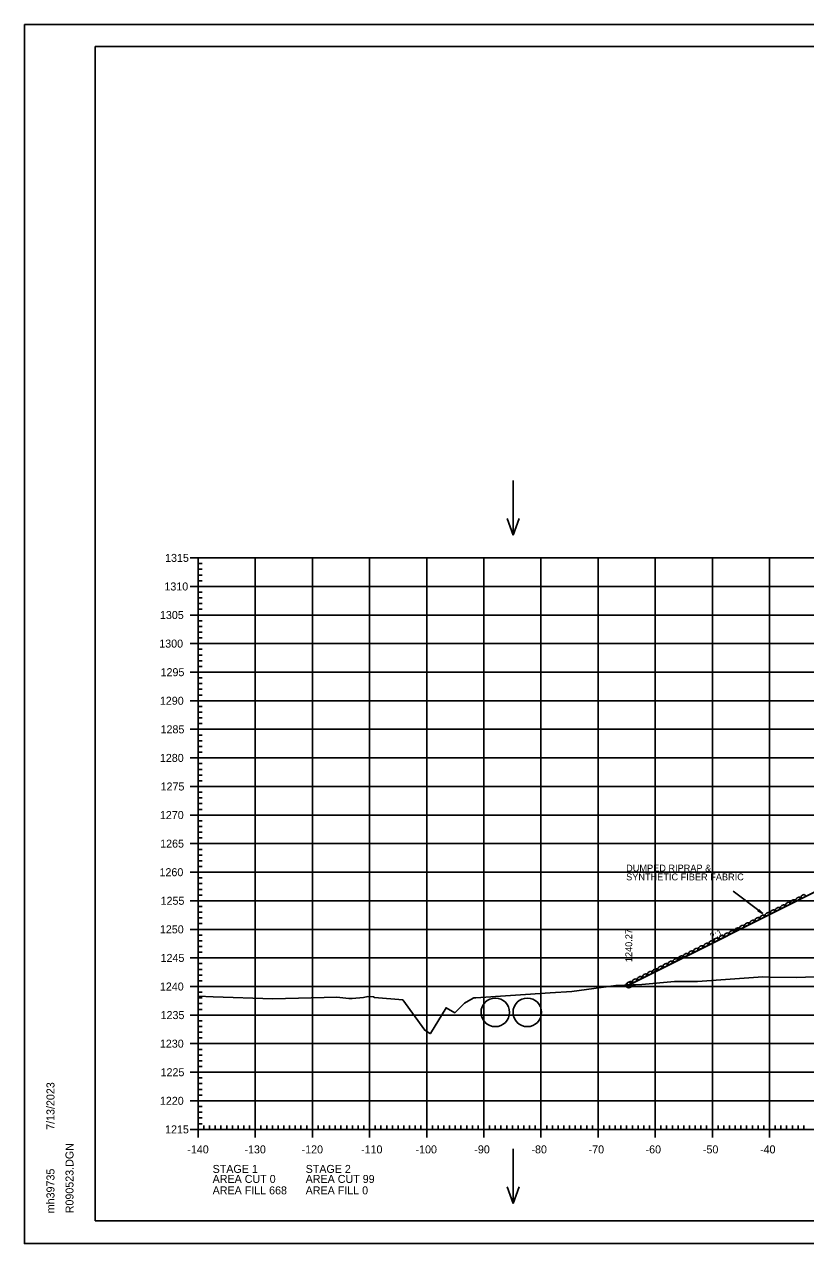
# Model space of a CAD drawing. Extents: x 1406028 to 1412453, y 321733 to 325986.
# Drawn here: x 1406419.5 to 1406556.2, y 323639.4 to 323852.7 of the extents above; entities that cross this region are included whole.
import ezdxf

# ---------------------------------------------------------------- set-up
doc = ezdxf.new("R2010")
doc.units = 0
for name, color, linetype in [('R_Axis', 7, 'Continuous'), ('R_Axis Annot', 7, 'Continuous'), ('R_Border', 7, 'Continuous'), ('R_Draft', 7, 'Continuous'), ('R_Exist Surface', 7, 'Continuous'), ('R_Fin Surface', 7, 'Continuous'), ('R_Fin Surface Annot', 7, 'Continuous'), ('R_Grid', 7, 'Continuous'), ('R_No Plot', 7, 'Continuous'), ('R_Proposed Const Limits', 7, 'Continuous'), ('R_Water', 7, 'Continuous'), ('R_Water Annot', 7, 'Continuous')]:
    doc.layers.add(name, color=color, linetype=linetype)

msp = doc.modelspace()

# ---------------------------------------------------------------- linework, layer by layer
at = {"layer": 'R_Axis'}
for p, q in [((1406448.49, 323759.36), (1406451.29, 323759.36)), ((1406449.89, 323659.36), (1406449.89, 323759.36)), ((1406449.89, 323758.36), (1406450.59, 323758.36)), ((1406449.89, 323757.36), (1406450.59, 323757.36)), ((1406449.89, 323756.36), (1406450.59, 323756.36)), ((1406449.89, 323755.36), (1406450.59, 323755.36)), ((1406448.49, 323754.36), (1406451.29, 323754.36)), ((1406449.89, 323753.36), (1406450.59, 323753.36)), ((1406449.89, 323752.36), (1406450.59, 323752.36)), ((1406449.89, 323751.36), (1406450.59, 323751.36)), ((1406448.49, 323749.36), (1406451.29, 323749.36)), ((1406449.89, 323750.36), (1406450.59, 323750.36)), ((1406449.89, 323748.36), (1406450.59, 323748.36)), ((1406449.89, 323747.36), (1406450.59, 323747.36)), ((1406449.89, 323746.36), (1406450.59, 323746.36)), ((1406448.49, 323744.36), (1406451.29, 323744.36)), ((1406449.89, 323745.36), (1406450.59, 323745.36)), ((1406449.89, 323743.36), (1406450.59, 323743.36)), ((1406449.89, 323742.36), (1406450.59, 323742.36)), ((1406449.89, 323741.36), (1406450.59, 323741.36)), ((1406449.89, 323740.36), (1406450.59, 323740.36)), ((1406448.49, 323739.36), (1406451.29, 323739.36)), ((1406449.89, 323738.36), (1406450.59, 323738.36)), ((1406449.89, 323737.36), (1406450.59, 323737.36)), ((1406449.89, 323736.36), (1406450.59, 323736.36)), ((1406448.49, 323734.36), (1406451.29, 323734.36)), ((1406449.89, 323735.36), (1406450.59, 323735.36)), ((1406449.89, 323733.36), (1406450.59, 323733.36)), ((1406449.89, 323732.36), (1406450.59, 323732.36)), ((1406449.89, 323731.36), (1406450.59, 323731.36)), ((1406448.49, 323729.36), (1406451.29, 323729.36)), ((1406449.89, 323730.36), (1406450.59, 323730.36)), ((1406449.89, 323728.36), (1406450.59, 323728.36)), ((1406449.89, 323727.36), (1406450.59, 323727.36)), ((1406449.89, 323726.36), (1406450.59, 323726.36)), ((1406449.89, 323725.36), (1406450.59, 323725.36)), ((1406448.49, 323724.36), (1406451.29, 323724.36)), ((1406449.89, 323723.36), (1406450.59, 323723.36)), ((1406449.89, 323722.36), (1406450.59, 323722.36)), ((1406449.89, 323721.36), (1406450.59, 323721.36)), ((1406448.49, 323719.36), (1406451.29, 323719.36)), ((1406449.89, 323720.36), (1406450.59, 323720.36)), ((1406449.89, 323718.36), (1406450.59, 323718.36)), ((1406449.89, 323717.36), (1406450.59, 323717.36)), ((1406449.89, 323716.36), (1406450.59, 323716.36)), ((1406448.49, 323714.36), (1406451.29, 323714.36)), ((1406449.89, 323715.36), (1406450.59, 323715.36)), ((1406449.89, 323713.36), (1406450.59, 323713.36)), ((1406449.89, 323712.36), (1406450.59, 323712.36)), ((1406449.89, 323711.36), (1406450.59, 323711.36)), ((1406449.89, 323710.36), (1406450.59, 323710.36)), ((1406448.49, 323709.36), (1406451.29, 323709.36)), ((1406449.89, 323708.36), (1406450.59, 323708.36)), ((1406449.89, 323707.36), (1406450.59, 323707.36)), ((1406449.89, 323706.36), (1406450.59, 323706.36)), ((1406448.49, 323704.36), (1406451.29, 323704.36)), ((1406449.89, 323705.36), (1406450.59, 323705.36)), ((1406449.89, 323703.36), (1406450.59, 323703.36)), ((1406449.89, 323702.36), (1406450.59, 323702.36)), ((1406448.49, 323699.36), (1406451.29, 323699.36)), ((1406449.89, 323701.36), (1406450.59, 323701.36)), ((1406449.89, 323700.36), (1406450.59, 323700.36)), ((1406449.89, 323698.36), (1406450.59, 323698.36)), ((1406449.89, 323697.36), (1406450.59, 323697.36)), ((1406449.89, 323696.36), (1406450.59, 323696.36)), ((1406449.89, 323695.36), (1406450.59, 323695.36)), ((1406448.49, 323694.36), (1406451.29, 323694.36)), ((1406449.89, 323693.36), (1406450.59, 323693.36)), ((1406449.89, 323692.36), (1406450.59, 323692.36)), ((1406449.89, 323691.36), (1406450.59, 323691.36)), ((1406448.49, 323689.36), (1406451.29, 323689.36)), ((1406449.89, 323690.36), (1406450.59, 323690.36)), ((1406449.89, 323688.36), (1406450.59, 323688.36)), ((1406449.89, 323687.36), (1406450.59, 323687.36)), ((1406448.49, 323684.36), (1406451.29, 323684.36)), ((1406449.89, 323686.36), (1406450.59, 323686.36)), ((1406449.89, 323685.36), (1406450.59, 323685.36)), ((1406449.89, 323683.36), (1406450.59, 323683.36)), ((1406449.89, 323682.36), (1406450.59, 323682.36)), ((1406449.89, 323681.36), (1406450.59, 323681.36)), ((1406449.89, 323680.36), (1406450.59, 323680.36)), ((1406448.49, 323679.36), (1406451.29, 323679.36)), ((1406449.89, 323678.36), (1406450.59, 323678.36)), ((1406449.89, 323677.36), (1406450.59, 323677.36)), ((1406449.89, 323676.36), (1406450.59, 323676.36)), ((1406448.49, 323674.36), (1406451.29, 323674.36)), ((1406449.89, 323675.36), (1406450.59, 323675.36)), ((1406449.89, 323673.36), (1406450.59, 323673.36)), ((1406449.89, 323672.36), (1406450.59, 323672.36)), ((1406449.89, 323671.36), (1406450.59, 323671.36)), ((1406449.89, 323670.36), (1406450.59, 323670.36)), ((1406448.49, 323669.36), (1406451.29, 323669.36)), ((1406449.89, 323668.36), (1406450.59, 323668.36)), ((1406449.89, 323667.36), (1406450.59, 323667.36)), ((1406449.89, 323666.36), (1406450.59, 323666.36)), ((1406449.89, 323665.36), (1406450.59, 323665.36)), ((1406448.49, 323664.36), (1406451.29, 323664.36)), ((1406449.89, 323663.36), (1406450.59, 323663.36)), ((1406449.89, 323662.36), (1406450.59, 323662.36)), ((1406449.89, 323661.36), (1406450.59, 323661.36)), ((1406448.49, 323659.36), (1406451.29, 323659.36)), ((1406449.89, 323657.96), (1406449.89, 323660.76)), ((1406449.89, 323660.36), (1406450.59, 323660.36)), ((1406449.89, 323659.36), (1406729.89, 323659.36)), ((1406450.89, 323659.36), (1406450.89, 323660.06)), ((1406451.89, 323659.36), (1406451.89, 323660.06)), ((1406452.89, 323659.36), (1406452.89, 323660.06)), ((1406453.89, 323659.36), (1406453.89, 323660.06)), ((1406454.89, 323659.36), (1406454.89, 323660.06)), ((1406455.89, 323659.36), (1406455.89, 323660.06)), ((1406456.89, 323659.36), (1406456.89, 323660.06)), ((1406457.89, 323659.36), (1406457.89, 323660.06)), ((1406458.89, 323659.36), (1406458.89, 323660.06)), ((1406459.89, 323657.96), (1406459.89, 323660.76)), ((1406460.89, 323659.36), (1406460.89, 323660.06)), ((1406461.89, 323659.36), (1406461.89, 323660.06)), ((1406462.89, 323659.36), (1406462.89, 323660.06)), ((1406463.89, 323659.36), (1406463.89, 323660.06)), ((1406464.89, 323659.36), (1406464.89, 323660.06)), ((1406465.89, 323659.36), (1406465.89, 323660.06)), ((1406466.89, 323659.36), (1406466.89, 323660.06)), ((1406467.89, 323659.36), (1406467.89, 323660.06)), ((1406468.89, 323659.36), (1406468.89, 323660.06)), ((1406469.89, 323657.96), (1406469.89, 323660.76)), ((1406470.89, 323659.36), (1406470.89, 323660.06)), ((1406471.89, 323659.36), (1406471.89, 323660.06)), ((1406472.89, 323659.36), (1406472.89, 323660.06)), ((1406473.89, 323659.36), (1406473.89, 323660.06)), ((1406474.89, 323659.36), (1406474.89, 323660.06)), ((1406475.89, 323659.36), (1406475.89, 323660.06)), ((1406476.89, 323659.36), (1406476.89, 323660.06)), ((1406477.89, 323659.36), (1406477.89, 323660.06)), ((1406478.89, 323659.36), (1406478.89, 323660.06)), ((1406479.89, 323657.96), (1406479.89, 323660.76)), ((1406480.89, 323659.36), (1406480.89, 323660.06)), ((1406481.89, 323659.36), (1406481.89, 323660.06)), ((1406482.89, 323659.36), (1406482.89, 323660.06)), ((1406483.89, 323659.36), (1406483.89, 323660.06)), ((1406484.89, 323659.36), (1406484.89, 323660.06)), ((1406485.89, 323659.36), (1406485.89, 323660.06)), ((1406486.89, 323659.36), (1406486.89, 323660.06)), ((1406487.89, 323659.36), (1406487.89, 323660.06)), ((1406488.89, 323659.36), (1406488.89, 323660.06)), ((1406489.89, 323657.96), (1406489.89, 323660.76)), ((1406490.89, 323659.36), (1406490.89, 323660.06)), ((1406491.89, 323659.36), (1406491.89, 323660.06)), ((1406492.89, 323659.36), (1406492.89, 323660.06)), ((1406493.89, 323659.36), (1406493.89, 323660.06)), ((1406494.89, 323659.36), (1406494.89, 323660.06)), ((1406495.89, 323659.36), (1406495.89, 323660.06)), ((1406496.89, 323659.36), (1406496.89, 323660.06)), ((1406497.89, 323659.36), (1406497.89, 323660.06)), ((1406498.89, 323659.36), (1406498.89, 323660.06)), ((1406499.89, 323657.96), (1406499.89, 323660.76)), ((1406500.89, 323659.36), (1406500.89, 323660.06)), ((1406501.89, 323659.36), (1406501.89, 323660.06)), ((1406502.89, 323659.36), (1406502.89, 323660.06)), ((1406503.89, 323659.36), (1406503.89, 323660.06)), ((1406504.89, 323659.36), (1406504.89, 323660.06)), ((1406505.89, 323659.36), (1406505.89, 323660.06)), ((1406506.89, 323659.36), (1406506.89, 323660.06)), ((1406507.89, 323659.36), (1406507.89, 323660.06)), ((1406508.89, 323659.36), (1406508.89, 323660.06)), ((1406509.89, 323657.96), (1406509.89, 323660.76)), ((1406510.89, 323659.36), (1406510.89, 323660.06)), ((1406511.89, 323659.36), (1406511.89, 323660.06)), ((1406512.89, 323659.36), (1406512.89, 323660.06)), ((1406513.89, 323659.36), (1406513.89, 323660.06)), ((1406514.89, 323659.36), (1406514.89, 323660.06)), ((1406515.89, 323659.36), (1406515.89, 323660.06)), ((1406516.89, 323659.36), (1406516.89, 323660.06)), ((1406517.89, 323659.36), (1406517.89, 323660.06)), ((1406518.89, 323659.36), (1406518.89, 323660.06)), ((1406519.89, 323657.96), (1406519.89, 323660.76)), ((1406520.89, 323659.36), (1406520.89, 323660.06)), ((1406521.89, 323659.36), (1406521.89, 323660.06)), ((1406522.89, 323659.36), (1406522.89, 323660.06)), ((1406523.89, 323659.36), (1406523.89, 323660.06)), ((1406524.89, 323659.36), (1406524.89, 323660.06)), ((1406525.89, 323659.36), (1406525.89, 323660.06)), ((1406526.89, 323659.36), (1406526.89, 323660.06)), ((1406527.89, 323659.36), (1406527.89, 323660.06)), ((1406528.89, 323659.36), (1406528.89, 323660.06)), ((1406529.89, 323657.96), (1406529.89, 323660.76)), ((1406530.89, 323659.36), (1406530.89, 323660.06)), ((1406531.89, 323659.36), (1406531.89, 323660.06)), ((1406532.89, 323659.36), (1406532.89, 323660.06)), ((1406533.89, 323659.36), (1406533.89, 323660.06)), ((1406534.89, 323659.36), (1406534.89, 323660.06)), ((1406535.89, 323659.36), (1406535.89, 323660.06)), ((1406536.89, 323659.36), (1406536.89, 323660.06)), ((1406537.89, 323659.36), (1406537.89, 323660.06)), ((1406538.89, 323659.36), (1406538.89, 323660.06)), ((1406539.89, 323657.96), (1406539.89, 323660.76)), ((1406540.89, 323659.36), (1406540.89, 323660.06)), ((1406541.89, 323659.36), (1406541.89, 323660.06)), ((1406542.89, 323659.36), (1406542.89, 323660.06)), ((1406543.89, 323659.36), (1406543.89, 323660.06)), ((1406544.89, 323659.36), (1406544.89, 323660.06)), ((1406545.89, 323659.36), (1406545.89, 323660.06)), ((1406546.89, 323659.36), (1406546.89, 323660.06)), ((1406547.89, 323659.36), (1406547.89, 323660.06)), ((1406548.89, 323659.36), (1406548.89, 323660.06)), ((1406549.89, 323657.96), (1406549.89, 323660.76)), ((1406550.89, 323659.36), (1406550.89, 323660.06)), ((1406551.89, 323659.36), (1406551.89, 323660.06)), ((1406552.89, 323659.36), (1406552.89, 323660.06)), ((1406553.89, 323659.36), (1406553.89, 323660.06)), ((1406554.89, 323659.36), (1406554.89, 323660.06)), ((1406555.89, 323659.36), (1406555.89, 323660.06))]:
    msp.add_line(p, q, dxfattribs=at)
at = {"layer": 'R_Border'}
for p, q in [((1406431.89, 323848.82), (1406748.07, 323848.82)), ((1406431.89, 323643.36), (1406431.89, 323848.82)), ((1406431.89, 323643.36), (1406431.89, 323643.36)), ((1406748.07, 323643.36), (1406431.89, 323643.36))]:
    msp.add_line(p, q, dxfattribs=at)
at = {"layer": 'R_Draft'}
for p, q in [((1406543.51, 323701.03), (1406548.74, 323697.11)), ((1406548.03, 323697.83), (1406547.85, 323697.59)), ((1406547.85, 323697.59), (1406548.74, 323697.11)), ((1406547.87, 323697.61), (1406548.61, 323697.21)), ((1406547.88, 323697.63), (1406548.47, 323697.31)), ((1406547.9, 323697.65), (1406548.34, 323697.41)), ((1406547.91, 323697.67), (1406548.2, 323697.51)), ((1406547.93, 323697.69), (1406548.07, 323697.61)), ((1406547.95, 323697.72), (1406548.07, 323697.61)), ((1406547.97, 323697.74), (1406548.2, 323697.51)), ((1406547.99, 323697.77), (1406548.34, 323697.41)), ((1406548, 323697.79), (1406548.47, 323697.31)), ((1406548.02, 323697.81), (1406548.61, 323697.21)), ((1406548.03, 323697.83), (1406548.74, 323697.11))]:
    msp.add_line(p, q, dxfattribs=at)
for centre in [(1406553.97, 323699.25), (1406554.87, 323699.69), (1406555.76, 323700.14), (1406549.5, 323697.01), (1406550.4, 323697.46), (1406551.29, 323697.9), (1406552.18, 323698.35), (1406553.08, 323698.8), (1406545.03, 323694.77), (1406545.92, 323695.22), (1406546.82, 323695.67), (1406547.71, 323696.12), (1406548.61, 323696.56), (1406540.56, 323692.54), (1406541.45, 323692.99), (1406542.35, 323693.43), (1406543.24, 323693.88), (1406544.14, 323694.33), (1406536.98, 323690.75), (1406537.87, 323691.2), (1406538.77, 323691.64), (1406539.66, 323692.09), (1406532.51, 323688.51), (1406533.4, 323688.96), (1406534.3, 323689.41), (1406535.19, 323689.85), (1406536.09, 323690.3), (1406528.04, 323686.28), (1406528.93, 323686.72), (1406529.82, 323687.17), (1406530.72, 323687.62), (1406531.61, 323688.07), (1406525.35, 323684.94), (1406526.25, 323685.38), (1406527.14, 323685.83)]:
    msp.add_ellipse(centre, major_axis=(0.371, 0.232), ratio=0.517889, dxfattribs=at)
at = {"layer": 'R_Exist Surface'}
msp.add_lwpolyline([(1406449.89, 323682.66), (1406452.5, 323682.56), (1406462.98, 323682.2), (1406474.15, 323682.48), (1406476.26, 323682.24), (1406476.85, 323682.24), (1406478.82, 323682.45), (1406479.62, 323682.62), (1406480.57, 323682.53), (1406480.75, 323682.44), (1406485.7, 323682.04), (1406489.56, 323676.71), (1406490.37, 323676.17), (1406490.49, 323676.14), (1406490.55, 323676.14), (1406493.28, 323680.65), (1406494.83, 323679.76), (1406496.51, 323681.42), (1406498.01, 323682.34), (1406498.13, 323682.36), (1406498.49, 323682.36), (1406511.53, 323683.24), (1406515.31, 323683.51), (1406523.02, 323684.52), (1406527.56, 323684.72), (1406533.26, 323685.25), (1406537.3, 323685.22), (1406548.7, 323686.08), (1406549.96, 323685.99), (1406554.63, 323685.95), (1406562.49, 323686.25)], dxfattribs=at)
at = {"layer": 'R_Fin Surface'}
msp.add_lwpolyline([(1406525.26, 323684.62), (1406528.59, 323686.29), (1406556.29, 323700.14), (1406556.66, 323700.32), (1406559.89, 323701.94), (1406560.35, 323702.02), (1406564.45, 323702.7), (1406565.84, 323702.56), (1406577.89, 323701.36), (1406579.13, 323701.23), (1406589.89, 323700.16), (1406600.7, 323699.08), (1406601.89, 323698.96), (1406602.71, 323698.87), (1406609.89, 323698.16), (1406610.92, 323697.99), (1406619.89, 323696.49), (1406620.04, 323696.44), (1406621.32, 323696.01), (1406622.56, 323695.6), (1406633.52, 323691.95), (1406635.02, 323692.26), (1406648.63, 323695.01)], dxfattribs=at)
at = {"layer": 'R_Grid'}
for p, q in [((1406449.89, 323759.36), (1406729.89, 323759.36)), ((1406449.89, 323659.36), (1406449.89, 323759.36)), ((1406459.89, 323659.36), (1406459.89, 323759.36)), ((1406469.89, 323659.36), (1406469.89, 323759.36)), ((1406479.89, 323659.36), (1406479.89, 323759.36)), ((1406489.89, 323659.36), (1406489.89, 323759.36)), ((1406499.89, 323659.36), (1406499.89, 323759.36)), ((1406509.89, 323659.36), (1406509.89, 323759.36)), ((1406519.89, 323659.36), (1406519.89, 323759.36)), ((1406529.89, 323659.36), (1406529.89, 323759.36)), ((1406539.89, 323659.36), (1406539.89, 323759.36)), ((1406549.89, 323659.36), (1406549.89, 323759.36)), ((1406449.89, 323754.36), (1406729.89, 323754.36)), ((1406449.89, 323749.36), (1406729.89, 323749.36)), ((1406449.89, 323744.36), (1406729.89, 323744.36)), ((1406449.89, 323739.36), (1406729.89, 323739.36)), ((1406449.89, 323734.36), (1406729.89, 323734.36)), ((1406449.89, 323729.36), (1406729.89, 323729.36)), ((1406449.89, 323724.36), (1406729.89, 323724.36)), ((1406449.89, 323719.36), (1406729.89, 323719.36)), ((1406449.89, 323714.36), (1406729.89, 323714.36)), ((1406449.89, 323709.36), (1406729.89, 323709.36)), ((1406449.89, 323704.36), (1406729.89, 323704.36)), ((1406449.89, 323699.36), (1406729.89, 323699.36)), ((1406449.89, 323694.36), (1406729.89, 323694.36)), ((1406449.89, 323689.36), (1406729.89, 323689.36)), ((1406449.89, 323684.36), (1406729.89, 323684.36)), ((1406449.89, 323679.36), (1406729.89, 323679.36)), ((1406449.89, 323674.36), (1406729.89, 323674.36)), ((1406449.89, 323669.36), (1406729.89, 323669.36)), ((1406449.89, 323664.36), (1406729.89, 323664.36)), ((1406449.89, 323659.36), (1406729.89, 323659.36))]:
    msp.add_line(p, q, dxfattribs=at)
at = {"layer": 'R_No Plot'}
for p, q in [((1406419.49, 323852.71), (1406752.82, 323852.71)), ((1406419.49, 323639.38), (1406752.82, 323639.38))]:
    msp.add_line(p, q, dxfattribs=at)
for points in [[(1406419.48, 323852.71), (1406752.82, 323852.71), (1406752.82, 323639.37), (1406419.48, 323639.37)], [(1406665.81, 323848.82), (1406685.43, 323848.82), (1406685.43, 323838.94), (1406701.54, 323838.94), (1406724.74, 323838.94), (1406724.74, 323814.6), (1406748.07, 323814.6), (1406748.07, 323643.36), (1406431.89, 323643.36), (1406431.89, 323848.82)]]:
    msp.add_lwpolyline(points, close=True, dxfattribs=at)
msp.add_lwpolyline([(1406556.31, 323700.14), (1406525.37, 323684.67), (1406525.37, 323684.62), (1406527.56, 323684.72), (1406533.26, 323685.25), (1406537.3, 323685.22), (1406548.7, 323686.08), (1406549.96, 323685.99), (1406554.63, 323685.95), (1406562.49, 323686.25)], dxfattribs=at)
msp.add_circle((1406525.26, 323684.62), 0.5, dxfattribs=at)
at = {"layer": 'R_Proposed Const Limits'}
msp.add_lwpolyline([(1406559.89, 323701.94), (1406525.26, 323684.62)], dxfattribs=at)
at = {"layer": 'R_Water'}
for centre in [(1406501.9, 323679.84), (1406507.5, 323679.84)]:
    msp.add_circle(centre, 2.5, dxfattribs=at)
at = {"layer": 'R_Water Annot'}
for p, q in [((1406505.01, 323772.88), (1406505.01, 323763.31)), ((1406505.01, 323763.31), (1406503.95, 323766.24)), ((1406505.01, 323763.31), (1406506.08, 323766.24)), ((1406505.01, 323655.95), (1406505.01, 323646.37)), ((1406505.01, 323646.37), (1406503.95, 323649.3)), ((1406505.01, 323646.37), (1406506.08, 323649.3))]:
    msp.add_line(p, q, dxfattribs=at)

# ---------------------------------------------------------------- texts
at = {"layer": 'R_Axis Annot'}
for s, p in [('1315', (1406444.11, 323758.66)), ('1310', (1406443.99, 323753.66)), ('1305', (1406443.21, 323748.66)), ('1300', (1406443.09, 323743.66)), ('1295', (1406443.32, 323738.66)), ('1290', (1406443.2, 323733.66)), ('1285', (1406443.32, 323728.66)), ('1280', (1406443.2, 323723.66)), ('1275', (1406443.32, 323718.66)), ('1270', (1406443.2, 323713.66)), ('1265', (1406443.25, 323708.66)), ('1260', (1406443.13, 323703.66)), ('1255', (1406443.32, 323698.66)), ('1250', (1406443.2, 323693.66)), ('1245', (1406443.32, 323688.66)), ('1240', (1406443.2, 323683.66)), ('1235', (1406443.32, 323678.66)), ('1230', (1406443.2, 323673.66)), ('1225', (1406443.32, 323668.66)), ('1220', (1406443.2, 323663.66)), ('1215', (1406444.11, 323658.66)), ('-140', (1406448, 323655.16)), ('-130', (1406458, 323655.16)), ('-120', (1406468, 323655.16)), ('-110', (1406478.4, 323655.16)), ('-100', (1406487.94, 323655.16)), ('-90', (1406498.23, 323655.16)), ('-80', (1406508.23, 323655.16)), ('-70', (1406518.23, 323655.16)), ('-60', (1406528.2, 323655.16)), ('-50', (1406538.23, 323655.16)), ('-40', (1406548.23, 323655.16)), ('STAGE 1', (1406452.43, 323651.74)), ('STAGE 2', (1406468.71, 323651.74)), ('AREA CUT 0', (1406452.43, 323649.99)), ('AREA CUT 99', (1406468.71, 323649.99)), ('AREA FILL 668', (1406452.43, 323647.99)), ('AREA FILL 0', (1406468.71, 323647.99))]:
    msp.add_text(s, height=1.4, dxfattribs=at).set_placement(p)
at = {"layer": 'R_Border'}
for s, p in [('7/13/2023', (1406424.75, 323659.28)), ('R090523.DGN', (1406428.08, 323644.68)), ('mh39735', (1406424.75, 323644.68))]:
    msp.add_text(s, height=1.4, rotation=90, dxfattribs=at).set_placement(p)
at = {"layer": 'R_Draft'}
for s, p in [('DUMPED RIPRAP &', (1406524.8, 323704.48)), ('SYNTHETIC FIBER FABRIC', (1406524.8, 323702.94))]:
    msp.add_text(s, height=1.2, dxfattribs=at).set_placement(p)
at = {"layer": 'R_Fin Surface Annot'}
for s, rotation, p in [('1240.27', 90, (1406525.86, 323688.62)), ('2:1', 26.5651, (1406539.81, 323692.46))]:
    msp.add_text(s, height=1.2, rotation=rotation, dxfattribs=at).set_placement(p)
at = {"layer": 'R_No Plot'}
for p in [(1406533.22, 323685.2), (1406548.66, 323686.03), (1406478.78, 323682.25), (1406479.57, 323682.57), (1406485.66, 323681.99), (1406496.46, 323681.37), (1406490.51, 323676.09)]:
    msp.add_text('+', height=0.1, dxfattribs=at).set_placement(p)

doc.saveas('drawing.dxf')
